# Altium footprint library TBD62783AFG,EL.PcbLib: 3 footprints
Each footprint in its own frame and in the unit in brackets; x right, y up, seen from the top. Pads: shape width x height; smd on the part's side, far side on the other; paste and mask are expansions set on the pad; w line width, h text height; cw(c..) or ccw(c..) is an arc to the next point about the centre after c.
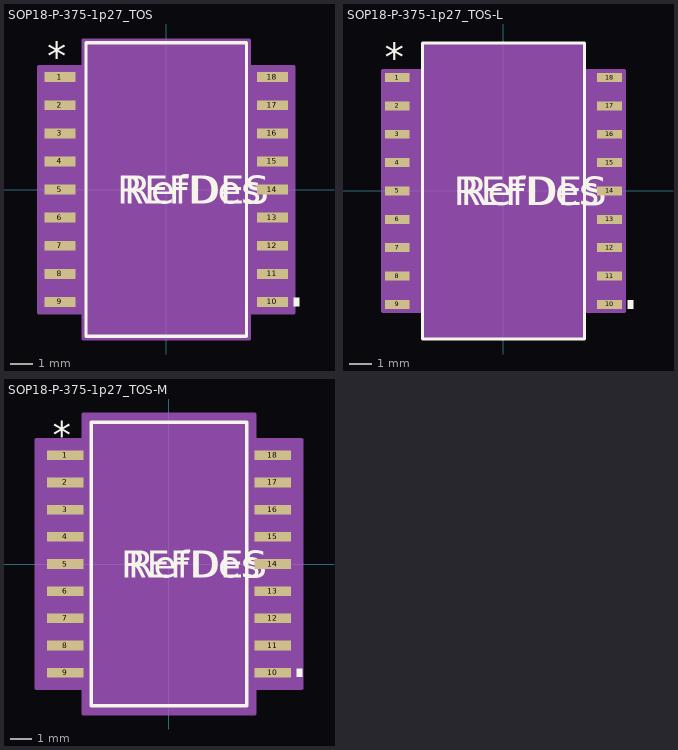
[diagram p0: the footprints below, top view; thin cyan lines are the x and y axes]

## SOP18-P-375-1p27_TOS [mm]
pads (18):
  rect 1.411x0.451 smd paste+0 mask+0: 1(-4.8,5.08) 2(-4.8,3.81) 3(-4.8,2.54) 4(-4.8,1.27) 5(-4.8,0) 6(-4.8,-1.27) 7(-4.8,-2.54) 8(-4.8,-3.81) 9(-4.8,-5.08) 10(4.8,-5.08) 11(4.8,-3.81) 12(4.8,-2.54) 13(4.8,-1.27) 14(4.8,0) 15(4.8,1.27) 16(4.8,2.54) 17(4.8,3.81) 18(4.8,5.08)
Top Overlay:
  region: 5.76,-4.889 6.014,-4.889 6.014,-5.271 5.76,-5.271
  lines w0.152: -3.627,-6.627 3.627,-6.627 3.627,6.627 -3.627,6.627 -3.627,-6.627
  text "REFDES" at -2.222,-0.635 h1.27
  text "*" at -5.371,5.404 h1.27
  text "RefDes" at -1.905,-0.635 h1.27
Mechanical 13:
  lines w0: -0.305,6.5 ccw(c0,6.5) 0.305,6.5
  lines w0.025: -5.15,-5.28 -5.15,-4.88 -3.5,-4.88 -3.5,-5.28 -5.15,-5.28 ; -5.15,-4.01 -5.15,-3.61 -3.5,-3.61 -3.5,-4.01 -5.15,-4.01 ; -5.15,-2.74 -5.15,-2.34 -3.5,-2.34 -3.5,-2.74 -5.15,-2.74 ; -5.15,-1.47 -5.15,-1.07 -3.5,-1.07 -3.5,-1.47 -5.15,-1.47 ; -5.15,-0.2 -5.15,0.2 -3.5,0.2 -3.5,-0.2 -5.15,-0.2 ; -5.15,1.07 -5.15,1.47 -3.5,1.47 -3.5,1.07 -5.15,1.07 ; -5.15,2.34 -5.15,2.74 -3.5,2.74 -3.5,2.34 -5.15,2.34 ; -5.15,3.61 -5.15,4.01 -3.5,4.01 -3.5,3.61 -5.15,3.61 ; -5.15,4.88 -5.15,5.28 -3.5,5.28 -3.5,4.88 -5.15,4.88 ; -3.5,-6.5 3.5,-6.5 3.5,6.5 -3.5,6.5 -3.5,-6.5 ; 3.5,-5.28 3.5,-4.88 5.15,-4.88 5.15,-5.28 3.5,-5.28 ; 3.5,-4.01 3.5,-3.61 5.15,-3.61 5.15,-4.01 3.5,-4.01 ; 3.5,-2.74 3.5,-2.34 5.15,-2.34 5.15,-2.74 3.5,-2.74 ; 3.5,-1.47 3.5,-1.07 5.15,-1.07 5.15,-1.47 3.5,-1.47 ; 3.5,-0.2 3.5,0.2 5.15,0.2 5.15,-0.2 3.5,-0.2 ; 3.5,1.07 3.5,1.47 5.15,1.47 5.15,1.07 3.5,1.07 ; 3.5,2.34 3.5,2.74 5.15,2.74 5.15,2.34 3.5,2.34 ; 3.5,3.61 3.5,4.01 5.15,4.01 5.15,3.61 3.5,3.61 ; 3.5,4.88 3.5,5.28 5.15,5.28 5.15,4.88 3.5,4.88
  text "*" at -3.436,5.154 h1.27
  text "RefDes2" at -2.222,-0.635 h1.27
Mechanical 15:
  region: -3.754,-5.559 -5.76,-5.559 -5.76,5.559 -3.754,5.559 -3.754,6.754 3.754,6.754 3.754,5.559 5.76,5.559 5.76,-5.559 3.754,-5.559 3.754,-6.754 -3.754,-6.754
  lines w0.152: -5.76,-5.559 -5.76,5.559 -3.754,5.559 -3.754,6.754 3.754,6.754 3.754,5.559 5.76,5.559 5.76,-5.559 3.754,-5.559 3.754,-6.754 -3.754,-6.754 -3.754,-5.559 -5.76,-5.559
3D body "SOP18-P-375-1p27_TOS.step": height 10.47, standoff 0, extent -6.47,-6.5 6.47,6.5

## SOP18-P-375-1p27_TOS-L [mm]
pads (18):
  rect 1.106x0.4 smd paste+0 mask+0: 1(-4.749,5.08) 2(-4.749,3.81) 3(-4.749,2.54) 4(-4.749,1.27) 5(-4.749,0) 6(-4.749,-1.27) 7(-4.749,-2.54) 8(-4.749,-3.81) 9(-4.749,-5.08) 10(4.749,-5.08) 11(4.749,-3.81) 12(4.749,-2.54) 13(4.749,-1.27) 14(4.749,0) 15(4.749,1.27) 16(4.749,2.54) 17(4.749,3.81) 18(4.749,5.08)
Top Overlay:
  region: 5.556,-4.889 5.81,-4.889 5.81,-5.271 5.556,-5.271
  lines w0.152: -3.627,-6.627 3.627,-6.627 3.627,6.627 -3.627,6.627 -3.627,-6.627
  text "REFDES" at -2.222,-0.635 h1.27
  text "*" at -5.321,5.353 h1.27
  text "RefDes" at -1.905,-0.635 h1.27
Mechanical 13:
  lines w0: -0.305,6.5 ccw(c0,6.5) 0.305,6.5
  lines w0.025: -5.15,-5.28 -5.15,-4.88 -3.5,-4.88 -3.5,-5.28 -5.15,-5.28 ; -5.15,-4.01 -5.15,-3.61 -3.5,-3.61 -3.5,-4.01 -5.15,-4.01 ; -5.15,-2.74 -5.15,-2.34 -3.5,-2.34 -3.5,-2.74 -5.15,-2.74 ; -5.15,-1.47 -5.15,-1.07 -3.5,-1.07 -3.5,-1.47 -5.15,-1.47 ; -5.15,-0.2 -5.15,0.2 -3.5,0.2 -3.5,-0.2 -5.15,-0.2 ; -5.15,1.07 -5.15,1.47 -3.5,1.47 -3.5,1.07 -5.15,1.07 ; -5.15,2.34 -5.15,2.74 -3.5,2.74 -3.5,2.34 -5.15,2.34 ; -5.15,3.61 -5.15,4.01 -3.5,4.01 -3.5,3.61 -5.15,3.61 ; -5.15,4.88 -5.15,5.28 -3.5,5.28 -3.5,4.88 -5.15,4.88 ; -3.5,-6.5 3.5,-6.5 3.5,6.5 -3.5,6.5 -3.5,-6.5 ; 3.5,-5.28 3.5,-4.88 5.15,-4.88 5.15,-5.28 3.5,-5.28 ; 3.5,-4.01 3.5,-3.61 5.15,-3.61 5.15,-4.01 3.5,-4.01 ; 3.5,-2.74 3.5,-2.34 5.15,-2.34 5.15,-2.74 3.5,-2.74 ; 3.5,-1.47 3.5,-1.07 5.15,-1.07 5.15,-1.47 3.5,-1.47 ; 3.5,-0.2 3.5,0.2 5.15,0.2 5.15,-0.2 3.5,-0.2 ; 3.5,1.07 3.5,1.47 5.15,1.47 5.15,1.07 3.5,1.07 ; 3.5,2.34 3.5,2.74 5.15,2.74 5.15,2.34 3.5,2.34 ; 3.5,3.61 3.5,4.01 5.15,4.01 5.15,3.61 3.5,3.61 ; 3.5,4.88 3.5,5.28 5.15,5.28 5.15,4.88 3.5,4.88
  text "*" at -3.436,5.154 h1.27
  text "RefDes2" at -2.222,-0.635 h1.27
Mechanical 15:
  region: -3.602,-5.382 -5.404,-5.382 -5.404,5.382 -3.602,5.382 -3.602,6.602 3.602,6.602 3.602,5.382 5.404,5.382 5.404,-5.382 3.602,-5.382 3.602,-6.602 -3.602,-6.602
  lines w0.152: -5.404,-5.382 -5.404,5.382 -3.602,5.382 -3.602,6.602 3.602,6.602 3.602,5.382 5.404,5.382 5.404,-5.382 3.602,-5.382 3.602,-6.602 -3.602,-6.602 -3.602,-5.382 -5.404,-5.382
3D body "SOP18-P-375-1p27_TOS.step": height 10.47, standoff 0, extent -6.47,-6.5 6.47,6.5

## SOP18-P-375-1p27_TOS-M [mil]
pads (18):
  rect 67.56x17.75 smd paste+0 mask+0: 1(-190.98,200) 2(-190.98,150) 3(-190.98,100) 4(-190.98,50) 5(-190.98,0) 6(-190.98,-50) 7(-190.98,-100) 8(-190.98,-150) 9(-190.98,-200) 10(190.98,-200) 11(190.98,-150) 12(190.98,-100) 13(190.98,-50) 14(190.98,0) 15(190.98,50) 16(190.98,100) 17(190.98,150) 18(190.98,200)
Top Overlay:
  region: 234.76,-192.5 244.76,-192.5 244.76,-207.5 234.76,-207.5
  lines w6: -142.8,-260.91 142.8,-260.91 142.8,260.91 -142.8,260.91 -142.8,-260.91
  text "REFDES" at -87.5,-25 h50
  text "*" at -213.48,212.75 h50
  text "RefDes" at -75,-25 h50
Mechanical 13:
  lines w0: -12,255.91 ccw(c0,255.91) 12,255.91
  lines w1: -202.76,-207.87 -202.76,-192.13 -137.8,-192.13 -137.8,-207.87 -202.76,-207.87 ; -202.76,-157.87 -202.76,-142.13 -137.8,-142.13 -137.8,-157.87 -202.76,-157.87 ; -202.76,-107.87 -202.76,-92.13 -137.8,-92.13 -137.8,-107.87 -202.76,-107.87 ; -202.76,-57.87 -202.76,-42.13 -137.8,-42.13 -137.8,-57.87 -202.76,-57.87 ; -202.76,-7.87 -202.76,7.87 -137.8,7.87 -137.8,-7.87 -202.76,-7.87 ; -202.76,42.13 -202.76,57.87 -137.8,57.87 -137.8,42.13 -202.76,42.13 ; -202.76,92.13 -202.76,107.87 -137.8,107.87 -137.8,92.13 -202.76,92.13 ; -202.76,142.13 -202.76,157.87 -137.8,157.87 -137.8,142.13 -202.76,142.13 ; -202.76,192.13 -202.76,207.87 -137.8,207.87 -137.8,192.13 -202.76,192.13 ; -137.8,-255.91 137.8,-255.91 137.8,255.91 -137.8,255.91 -137.8,-255.91 ; 137.8,-207.87 137.8,-192.13 202.76,-192.13 202.76,-207.87 137.8,-207.87 ; 137.8,-157.87 137.8,-142.13 202.76,-142.13 202.76,-157.87 137.8,-157.87 ; 137.8,-107.87 137.8,-92.13 202.76,-92.13 202.76,-107.87 137.8,-107.87 ; 137.8,-57.87 137.8,-42.13 202.76,-42.13 202.76,-57.87 137.8,-57.87 ; 137.8,-7.87 137.8,7.87 202.76,7.87 202.76,-7.87 137.8,-7.87 ; 137.8,42.13 137.8,57.87 202.76,57.87 202.76,42.13 137.8,42.13 ; 137.8,92.13 137.8,107.87 202.76,107.87 202.76,92.13 137.8,92.13 ; 137.8,142.13 137.8,157.87 202.76,157.87 202.76,142.13 137.8,142.13 ; 137.8,192.13 137.8,207.87 202.76,207.87 202.76,192.13 137.8,192.13
  text "*" at -135.3,202.91 h50
  text "RefDes2" at -87.5,-25 h50
Mechanical 15:
  region: -157.8,-228.87 -244.76,-228.87 -244.76,228.87 -157.8,228.87 -157.8,275.91 157.8,275.91 157.8,228.87 244.76,228.87 244.76,-228.87 157.8,-228.87 157.8,-275.91 -157.8,-275.91
  lines w6: -244.76,-228.87 -244.76,228.87 -157.8,228.87 -157.8,275.91 157.8,275.91 157.8,228.87 244.76,228.87 244.76,-228.87 157.8,-228.87 157.8,-275.91 -157.8,-275.91 -157.8,-228.87 -244.76,-228.87
3D body "SOP18-P-375-1p27_TOS.step": height 412.13, standoff 0, extent -254.72,-255.91 254.72,255.91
